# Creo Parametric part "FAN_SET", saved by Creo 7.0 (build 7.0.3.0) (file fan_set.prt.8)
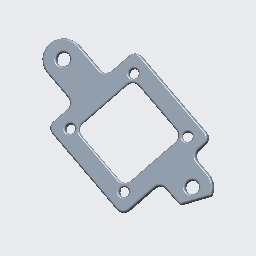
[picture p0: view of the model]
Units: millimeter Kilogram Sec (mmKs); MM, KILOGRAM, SECS

Created from: XX_SOLID_PART_MMKS_ABS.PRT

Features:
  1. coordinate system
  2. datum plane "RIGHT"
  3. datum plane "TOP"
  4. datum plane "FRONT"
  5. extrusion "Extrude 1"
  6. extruded cut "Extrude 2"
  7. extruded cut "Extrude 3"
  8. extruded cut "Extrude 4"
  9. extruded cut "Extrude 5"
  10. extruded cut "Extrude 6"
  11. round "Round 1"
  12. round "Round 2"
  13. round "Round 3"
  14. round "Round 4"
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
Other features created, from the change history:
  round "Round 5"
  extruded cut "Extrude 7"
  round "Round 6"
